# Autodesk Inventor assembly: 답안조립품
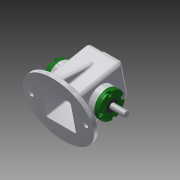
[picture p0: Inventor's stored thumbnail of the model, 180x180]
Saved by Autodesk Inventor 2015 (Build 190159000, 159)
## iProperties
Created: 2017-07
Part Number: 답안조립품
Document SubType Name: Assembly
Designer: C03
Author: C03
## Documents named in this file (13)
- C:\Users\C03\Desktop\470707V1016\답안조립품.iam
- C:\Users\C03\Desktop\470707V1016\본체.ipt
- C:\Users\C03\Desktop\470707V1016\뒤커버.ipt
- C:\Users\C03\Desktop\470707V1016\앞커버.ipt
- C:\Users\C03\Desktop\470707V1016\베어링 12 x 32 x 10.ipt
- C:\Users\C03\Desktop\470707V1016\오일실 12 25 7.ipt
- C:\Users\C03\Desktop\470707V1016\부시.ipt
- C:\Users\C03\Desktop\470707V1016\편심축.ipt
- C:\Users\C03\Desktop\470707V1016\링크.ipt
- C:\Users\C03\Desktop\470707V1016\슬라이드.ipt
- C:\Users\C03\Desktop\470707V1016\핀 5 x 18.ipt
- C:\Users\C03\Desktop\470707V1016\고정핀 1.2 x  8.ipt
- C:\Users\C03\Desktop\470707V1016\볼트 M4 x 12.ipt
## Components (2 placed, 2 different names)
1. 핀 5 x 18:1
2. 고정핀 1.2 x  8:1
